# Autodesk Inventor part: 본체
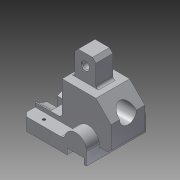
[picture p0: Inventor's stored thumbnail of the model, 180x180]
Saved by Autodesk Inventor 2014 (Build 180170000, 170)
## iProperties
Created: 2016-11
Part Number: 본체
Material: 알루미늄 6061
Document SubType Name: Modeling
Designer: USER
Density: 2.71 g/cm^3
Appearance: 알루미늄 - 평지
Mass: 462.977 g
Surface Area: 317.525 cm^2
Volume: 170.84 cm^3
Author: USER
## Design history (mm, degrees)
sketch "스케치1"
  geometry: L1 (0, 16)-(0, 42); L2 (0, 42)-(18, 60); L3 (18, 60)-(58, 60); L4 (58, 60)-(58, 20); L5 (58, 20)-(90, 20); L6 (90, 20)-(90, 0); L7 (90, 0)-(40, 0); L8 (40, 0)-(40, 12); L9 (40, 12)-(4, 12); L10 (4, 12)-(0, 16); 2 further points
  constraints: 20 end point, 4 parallel, 2 horizontal alignment, 2 perpendicular, 2 point on line, 1 vertical, 1 vertical alignment
  dimensions: "d0" = 60 distance between parallel lines of L7 L3; "d1" = 48 distance between parallel lines of L9 L3; "d2" = 20 distance of L5.end L6.end; "d3" = 90 distance between parallel lines of L1 L6; "d4" = 58 distance between parallel lines of L1 L4; "d5" = 45 deg angle of L2 L3; "d6" = 18 horizontal distance of L1.end L2.end; "d7" = 40 distance from line of point (0, 0) L8; "d21" = 4 distance of L9.end point (0, 12); "d22" = 4 distance of L1.start point (0, 12) (= d21)
extrude "돌출1" new body sketch "스케치1" stored distance "d8" = 40; taper "d9" = 0 deg
sketch "스케치2"
  geometry: L1 (14, 15)-(14, 0); L2 (14, 0)-(17, 0); L3 (17, 0)-(17, 7); L4 (17, 7)-(37, 7); L5 (37, 7)-(37, 0); L6 (37, 0)-(90, 0); L7 (90, 15)-(90, 0); L8 (90, 15)-(40, 15); A1 r 13 centre (27, 15) between (40, 15) and (14, 15); 1 further point
  constraints: 16 end point, 3 perpendicular, 2 parallel, 2 point on circle, 1 centre point, 1 horizontal alignment, 1 tangent, 1 vertical, 1 vertical alignment
  dimensions: "d10" = 26 diameter of A1; "d11" = 15 vertical distance of point (0, 0) A1.centre; "d12" = 15 distance of L1.start L1.end; "d13" = 3 distance of L1.end L2.end; "d14" = 7 distance of L2.end L3.end; "d15" = 20 distance of L3.end L4.end; "d17" = 15 distance of L7.start L6.end; "d18" = 37 distance from line of point (0, 0) L5
extrude "돌출2" join sketch "스케치2" stored distance "d19" = 70; taper "d20" = 0 deg
sketch "스케치4"
  geometry: L1 (32, 90)-(49, 90); L2 (53, 86)-(53, 56.953); L3 (53, 56.953)-(28, 56.953); L4 (28, 56.953)-(28, 86); L5 (90, 0)-(37, 0) reference; L6 (58, 60)-(58, 20) reference; L7 (32, 90)-(28, 86); L8 (49, 90)-(53, 86); 3 further points
  constraints: 12 end point, 4 point on line, 2 parallel, 1 horizontal, 1 perpendicular
  dimensions: "d32" = 25 distance of point (28, 90) point (53, 90); "d33" = 90 distance between parallel lines of L5 L1; "d35" = 5 distance between parallel lines of L2 L6; "d36" = 56.95258 distance between parallel lines of L5 L3; "d37" = 4 distance of L1.start point (28, 90); "d38" = 4 distance of L4.end point (28, 90) (= d37); "d39" = 4 distance of L1.end point (53, 90) (= d37); "d40" = 4 distance of L2.start point (53, 90) (= d39)
extrude "돌출3" join sketch "스케치4" stored distance "d41" = 20; taper "d42" = 0 deg
sketch "스케치5"
  geometry: L1 (-45, 55)-(-45, 40) reference; L2 (-60, 55)-(-60, -15) reference; 2 further points
  constraints: 1 horizontal alignment
  dimensions: "d62" = 42 distance from line of L2 point (-18, 20)
hole "구멍2" sketch "스케치5" at (-18, 20) diameter "d45" = 20; stored, may be unused: countersink angle "d49" = 90 deg, drill point angle "d51" = 118 deg; dims "d46" = 6, "d47" = 29, "d48" = 7, "d50" = 8
sketch "스케치6"
  geometry: L1 (-28, -86)-(-28, -60) reference; L2 (-37, 0)-(-90, 0) reference; 2 further points
  dimensions: "d52" = 12.5 distance from line of L1 point (-40.5, -77); "d53" = 77 distance from line of L2 point (-40.5, -77)
hole "구멍3" sketch "스케치6" at (-40.5, -77) diameter "d54" = 8; stored, may be unused: countersink angle "d58" = 90 deg, drill point angle "d60" = 118 deg; dims "d55" = 6, "d56" = 29, "d57" = 7, "d59" = 8
sketch "스케치7"
  geometry: L1 (-5, 0)-(-5, -15) reference; L2 (-6.373, 26)-(-20, 26); L3 (-20, 26)-(-20, 14); L4 (-20, 14)-(-6.373, 14); C1 r 14.5 at (22, 20) reference; A1 r 29 centre (22, 20) between (-6.373, 14) and (-6.373, 26); 3 further points
  constraints: 6 end point, 2 perpendicular, 2 point on circle, 1 centre point, 1 coincident, 1 horizontal alignment, 1 midpoint, 1 parallel, 1 vertical alignment
  dimensions: "d63" = 58 diameter of A1; "d66" = 12 distance of L2.end L3.end
extrude "돌출4" cut sketch "스케치7" distance "d67" = 18; taper "d68" = 0 deg
sketch "스케치8"
  geometry: L1 (0, 0)-(0, -15) reference; 3 further points
  constraints: 1 vertical alignment
  dimensions: "d69" = 55 distance of point (18, 47.5) point (18, -7.5); "d70" = 18 distance from line of point (18, -7.5) L1; "d71" = 27.5 vertical distance of point (90, 20) point (18, -7.5)
hole "구멍4" sketch "스케치8" at (18, -7.5), (18, 47.5) diameter "d72" = 3.242; stored, may be unused: countersink angle "d76" = 90 deg, drill point angle "d78" = 118 deg; dims "d73" = 6, "d74" = 29, "d75" = 7, "d77" = 8
chamfer "모따기1" distance "d79" = 5; stored, may be unused: second distance "d80" = 2, angle "d81" = 45 deg
chamfer "모따기2" distance "d82" = 1; stored, may be unused: second distance "d83" = 2, angle "d84" = 45 deg
fillet "모깎기1" dims "d85" = 3
fillet "모깎기2" dims "d86" = 5
fillet "모깎기3" dims "d87" = 3
sketch "스케치9"
  geometry: L1 (-58, -23)-(-58, -60) reference; L2 (-58, -60)-(-18, -60) reference; 2 further points
  constraints: 1 other
  dimensions: "d88" = 25 distance from line of L1 point (-33, -42); "d89" = 18 distance from line of L2 point (-33, -42)
extrude "돌출5" join sketch "스케치9" distance "d90" = 0.5; taper "d91" = 0 deg
chamfer "모따기3" distance "d92" = 1; stored, may be unused: second distance "d93" = 2, angle "d94" = 45 deg
chamfer "모따기4" distance "d95" = 1; stored, may be unused: second distance "d96" = 2, angle "d97" = 45 deg
node "솔리드1"
